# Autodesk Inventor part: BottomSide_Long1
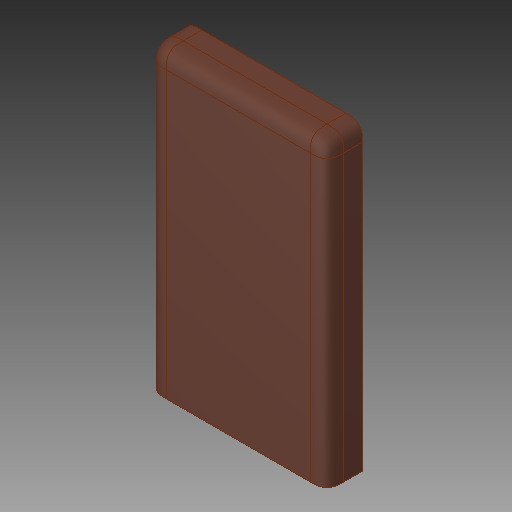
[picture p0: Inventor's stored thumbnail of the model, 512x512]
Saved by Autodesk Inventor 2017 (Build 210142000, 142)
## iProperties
Created: 2017-05
Part Number: BottomSide_Long1
Material: Generic
Document SubType Name: Modeling
Designer: Savy
Density: 1 g/cm^3
Appearance: Default
Author: Savy
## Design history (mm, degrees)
feature "SOLID1"
body "Solid1"
